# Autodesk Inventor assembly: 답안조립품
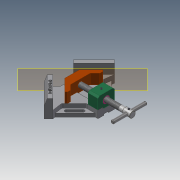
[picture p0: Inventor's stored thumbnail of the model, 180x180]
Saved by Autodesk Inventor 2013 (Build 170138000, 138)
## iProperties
Created: 2020-05
Part Number: 답안조립품
Document SubType Name: Assembly
Designer: user
Author: user
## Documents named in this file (11)
- C:\Users\user\Desktop\700506V1006\답안조립품.iam
- C:\Users\user\Desktop\700506V1006\본체.ipt
- C:\Users\user\Desktop\700506V1006\리드스크류.ipt
- C:\Users\user\Desktop\700506V1006\멈춤나사 M4x5.ipt
- C:\Users\user\Desktop\700506V1006\멈춤나사 M4x10.ipt
- C:\Users\user\Desktop\700506V1006\볼트 M4x16.ipt
- C:\Users\user\Desktop\700506V1006\부시.ipt
- C:\Users\user\Desktop\700506V1006\서포트.ipt
- C:\Users\user\Desktop\700506V1006\조.ipt
- C:\Users\user\Desktop\700506V1006\평행 핀 2.5x24.ipt
- C:\Users\user\Desktop\700506V1006\핸들.ipt
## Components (1 placed, 1 different names)
1. 핸들:1
